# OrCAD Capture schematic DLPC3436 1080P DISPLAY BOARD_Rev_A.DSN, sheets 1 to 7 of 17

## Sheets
1 P10: DMD Connection: size D
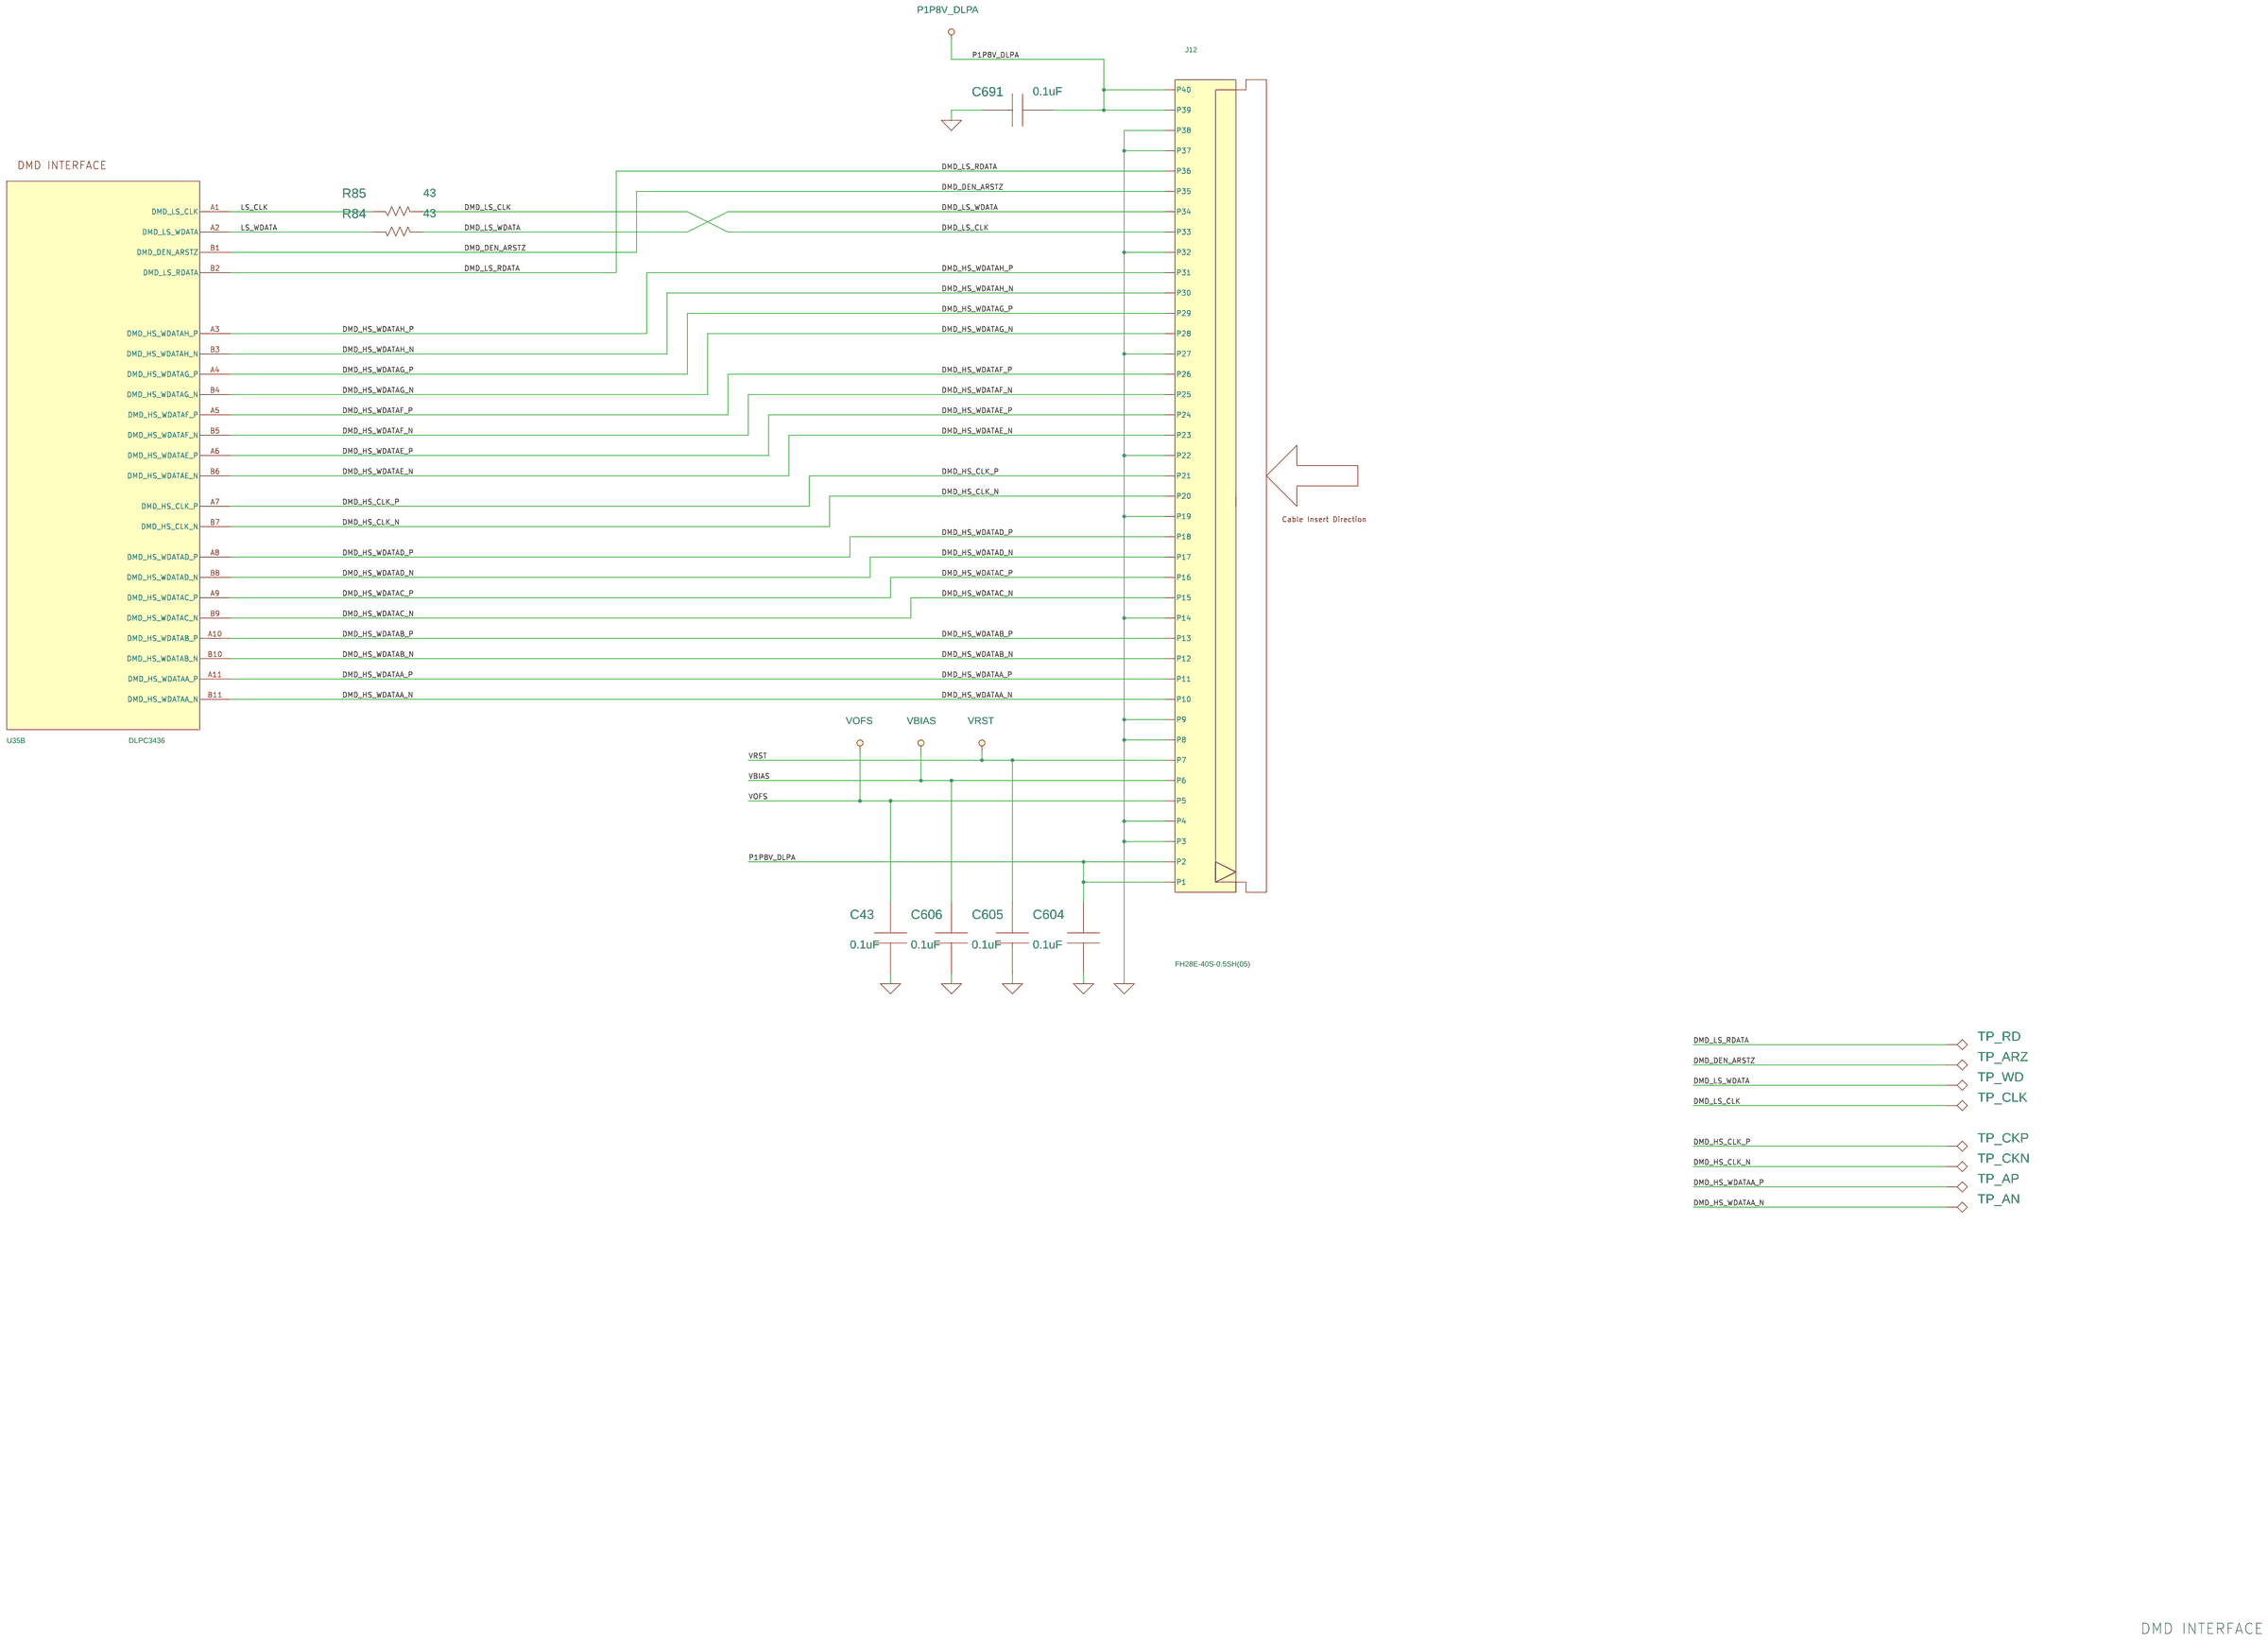
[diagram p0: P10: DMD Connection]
2 P08: FPGA Power: size D
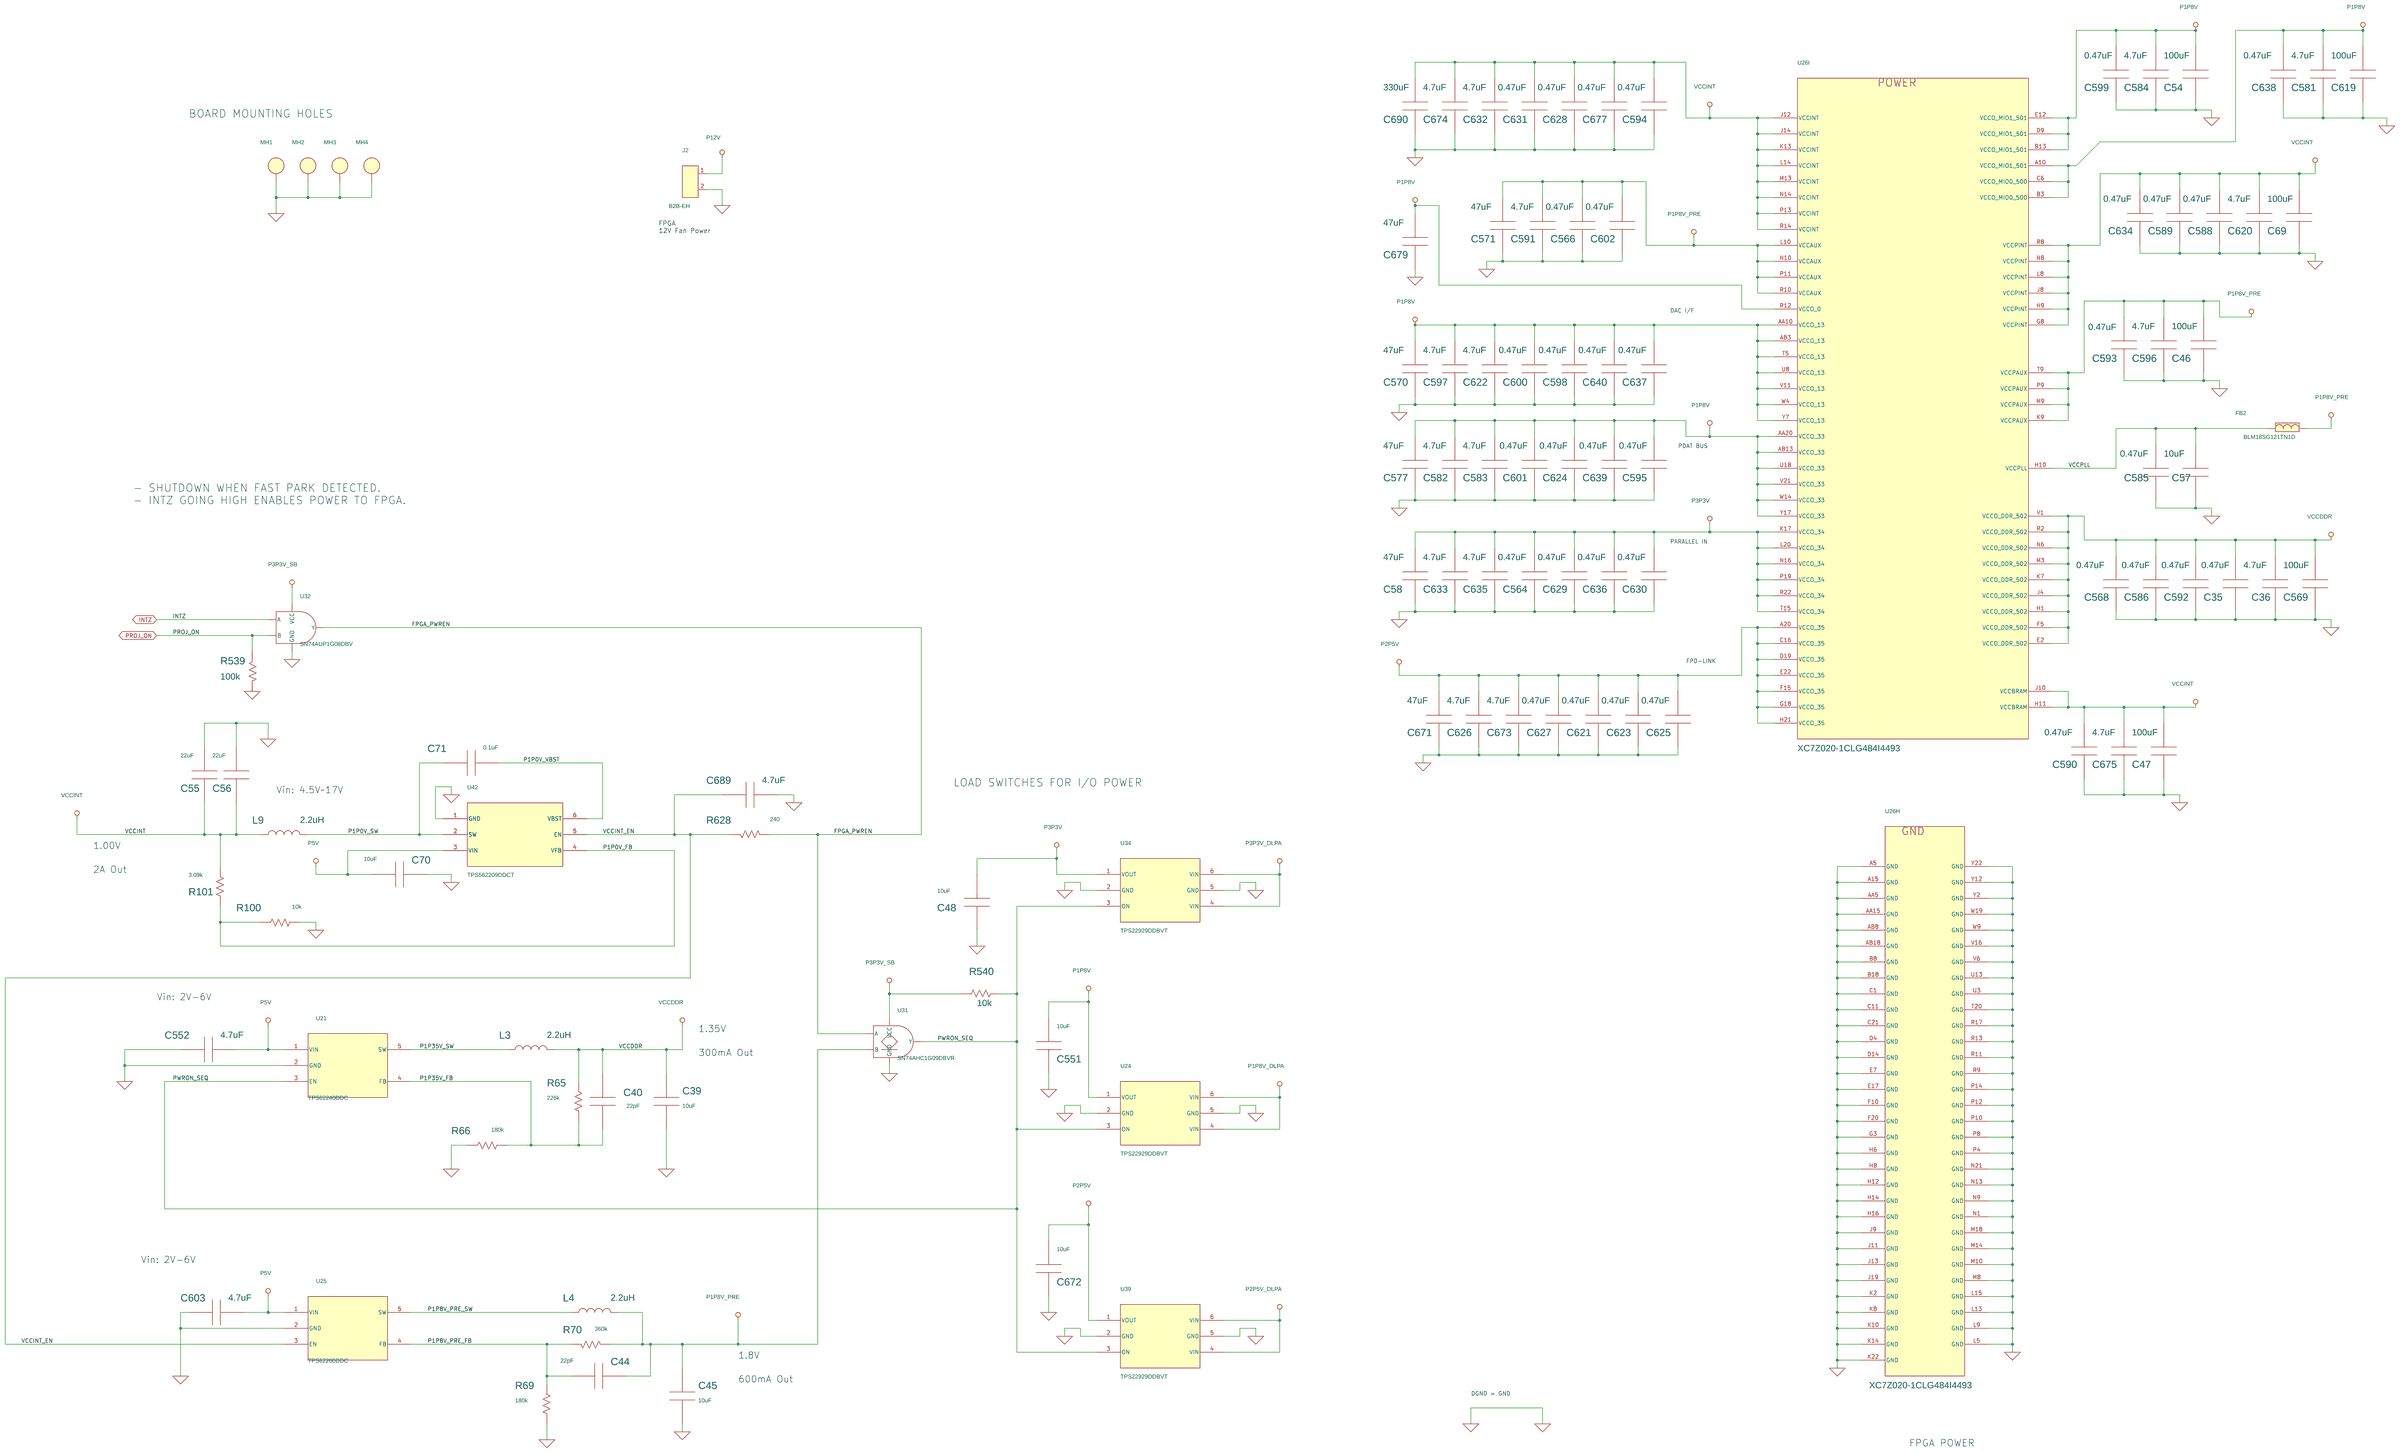
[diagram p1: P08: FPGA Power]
3 P16: Revisions
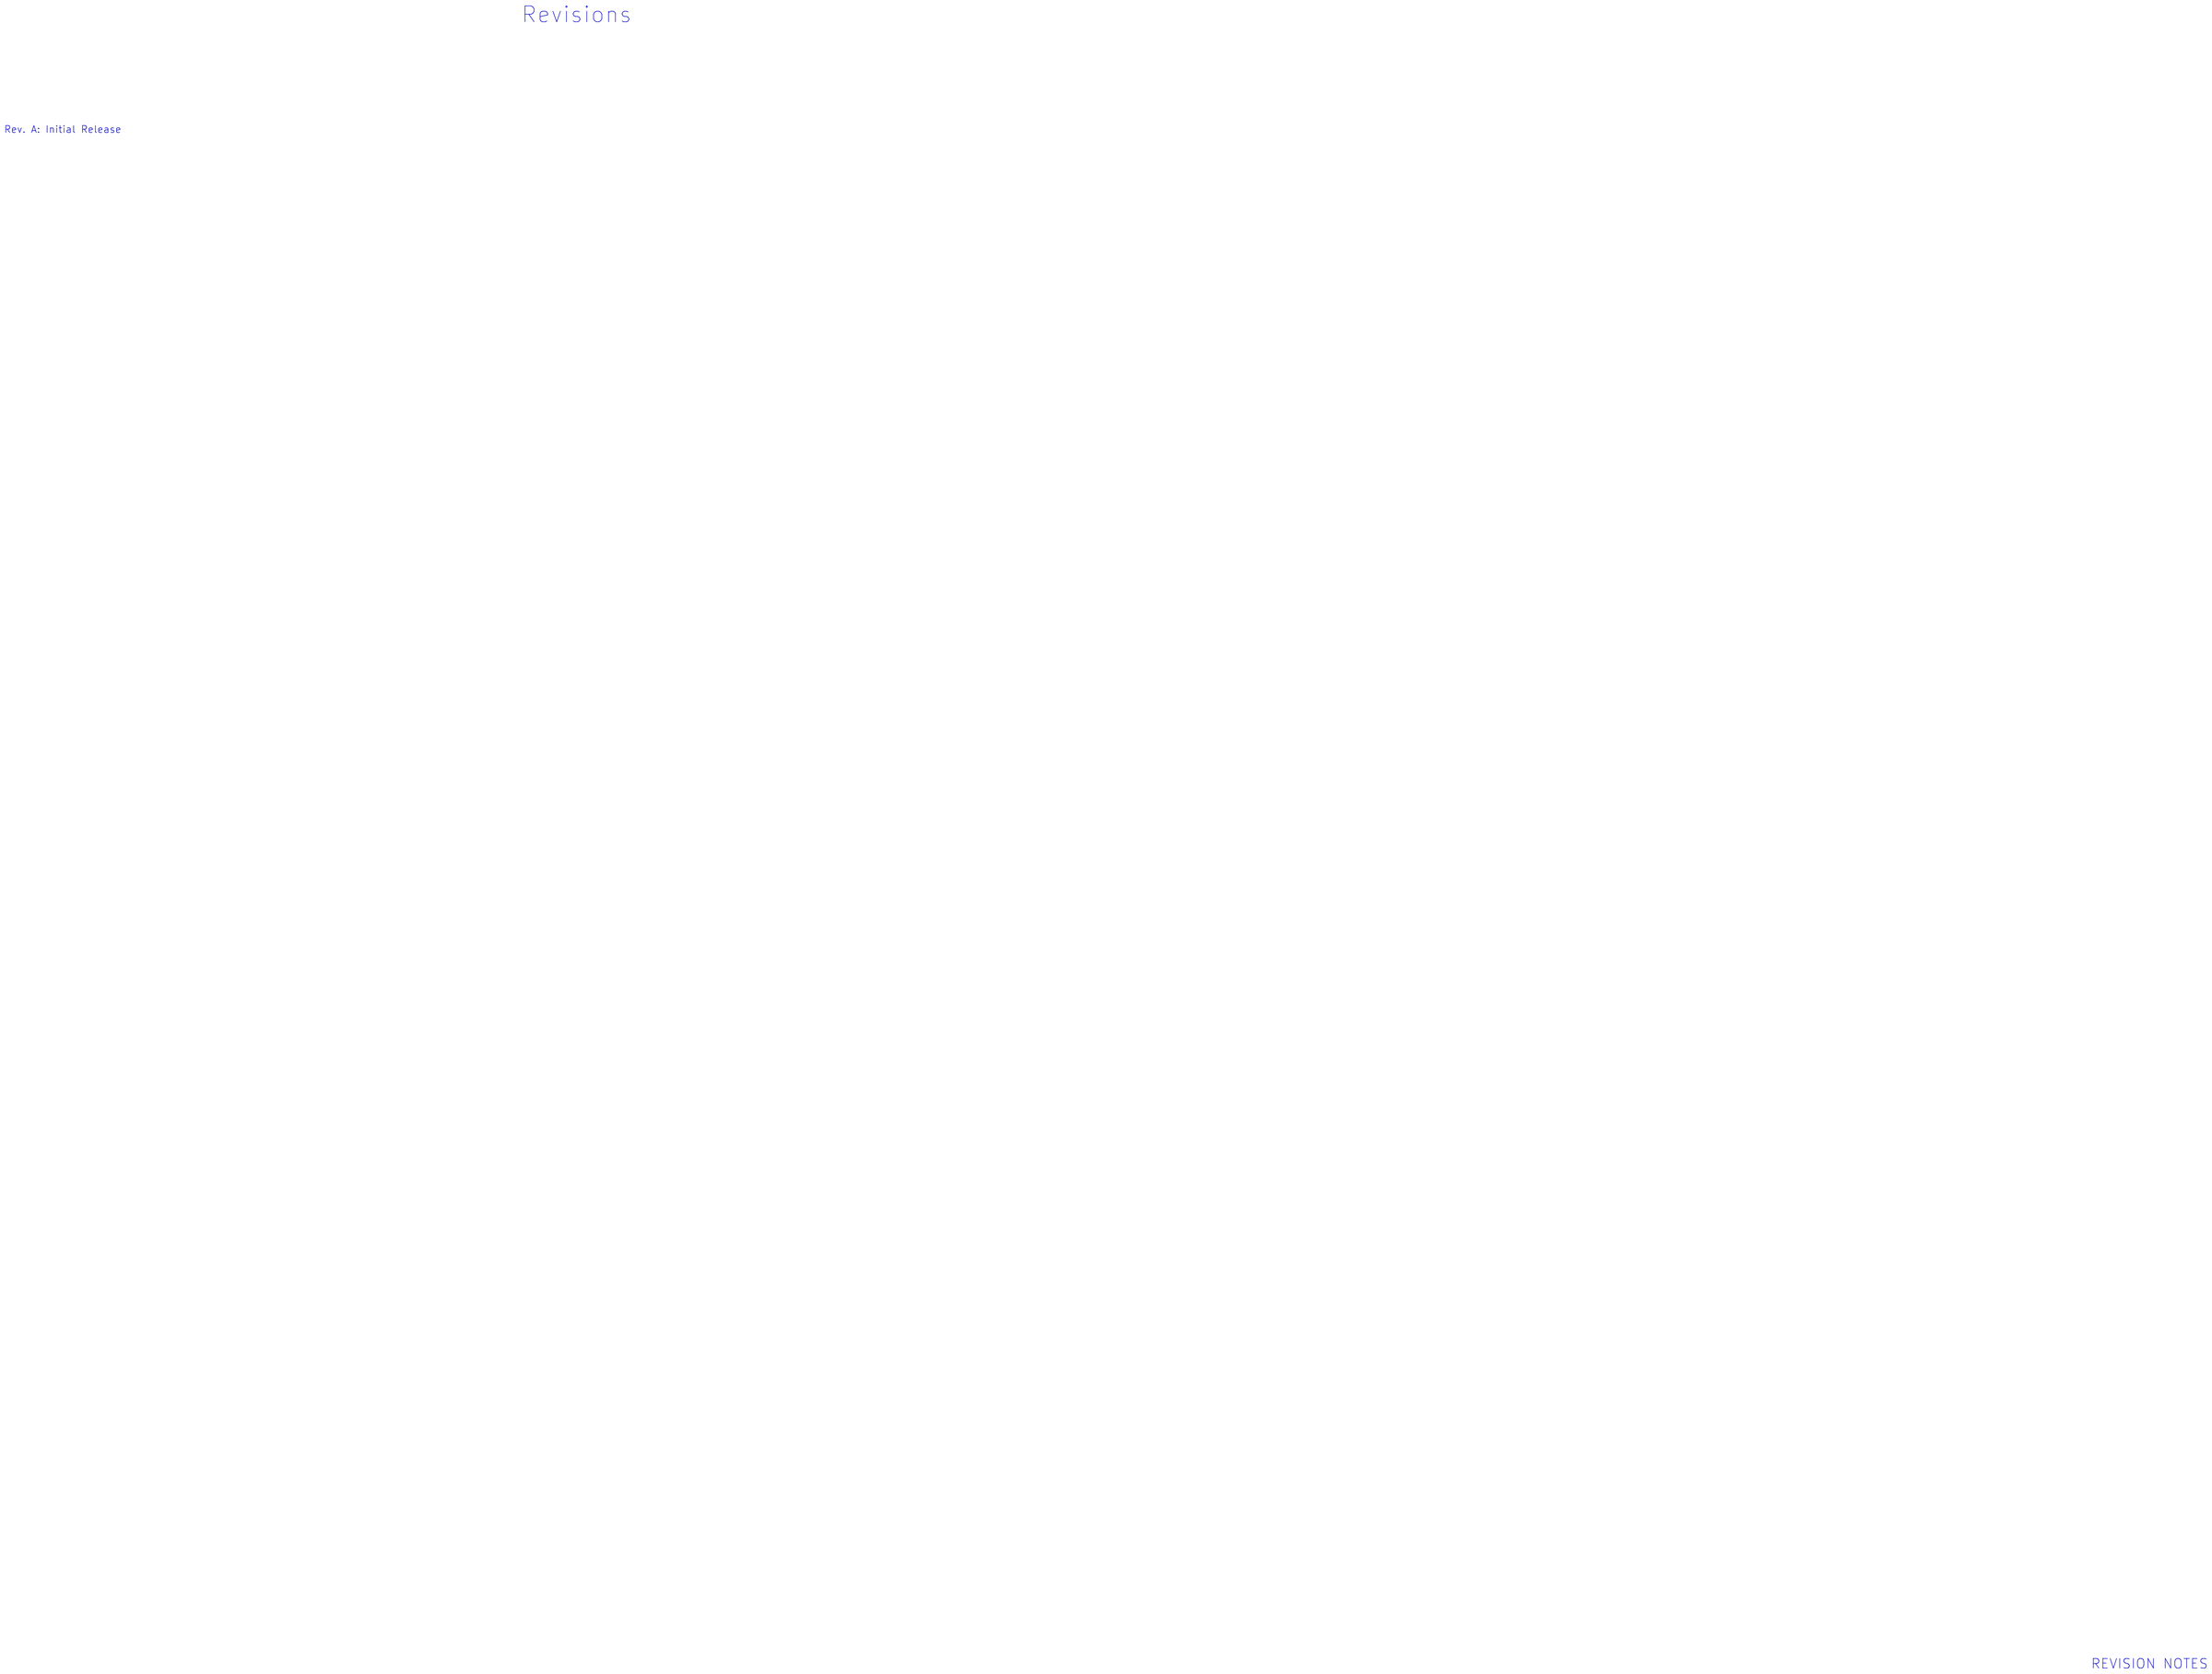
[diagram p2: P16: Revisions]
4 P11: ASIC GPIO: size D
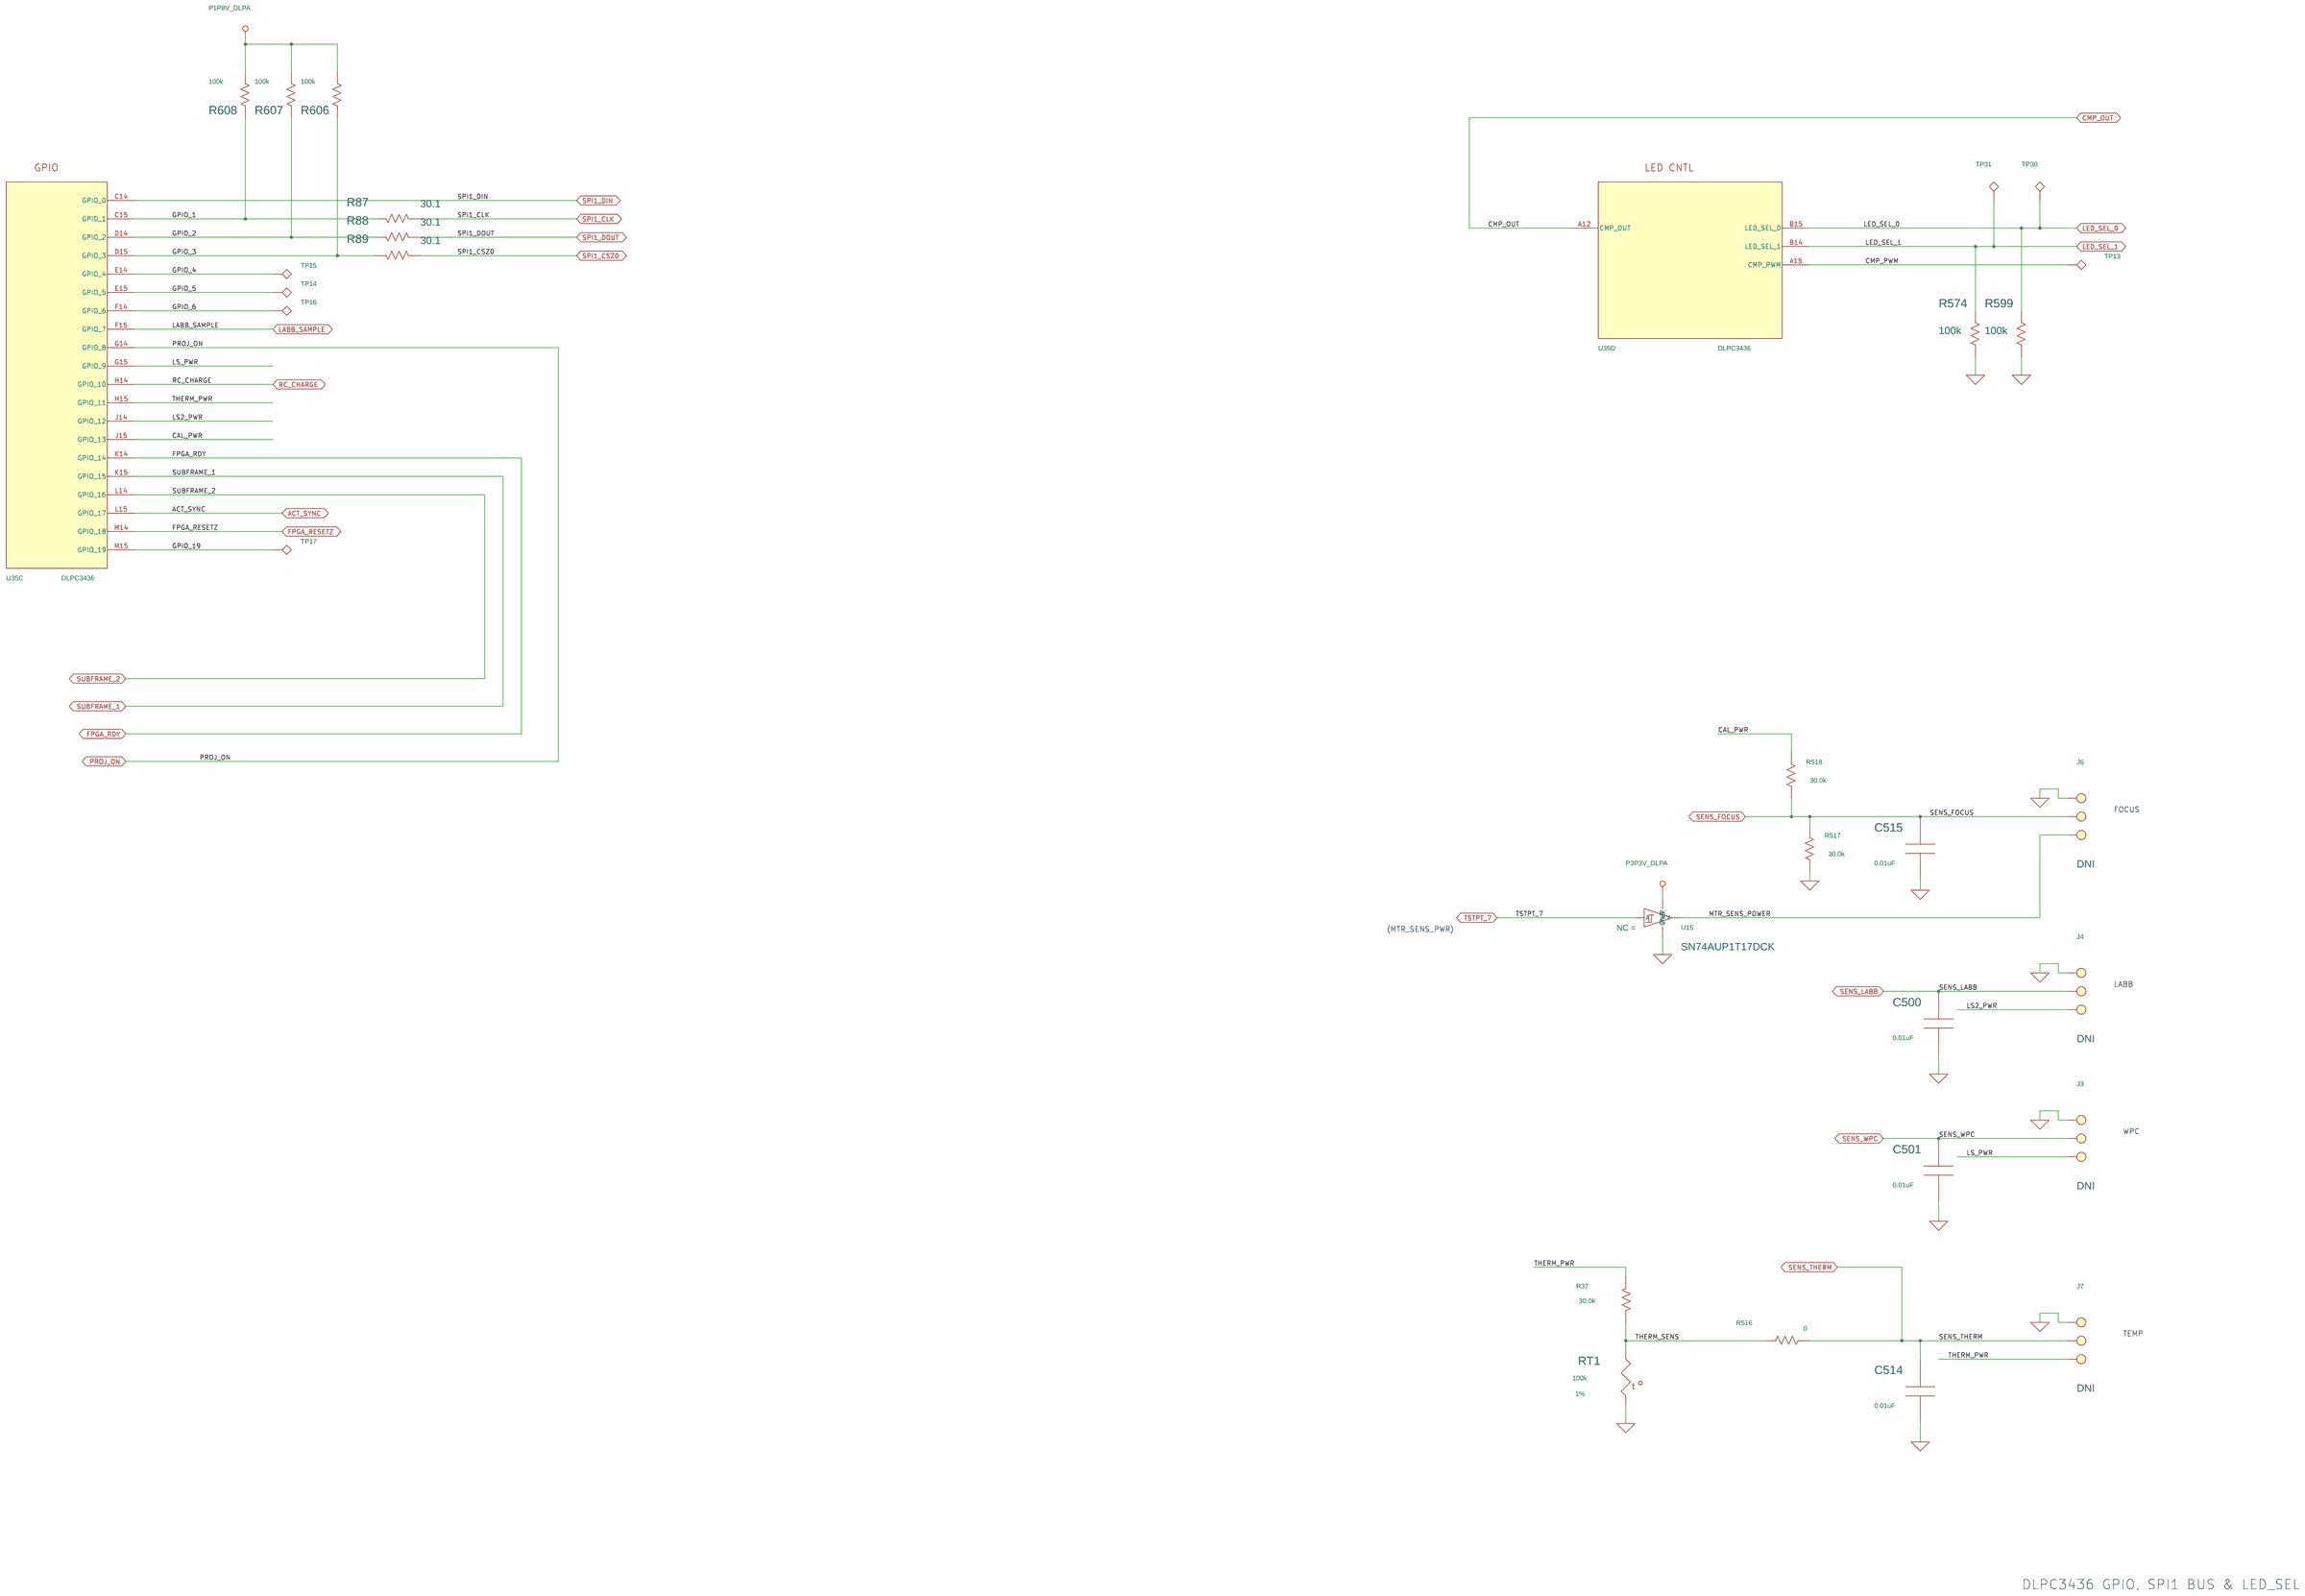
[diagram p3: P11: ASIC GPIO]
5 P01: Title Page: rev: A
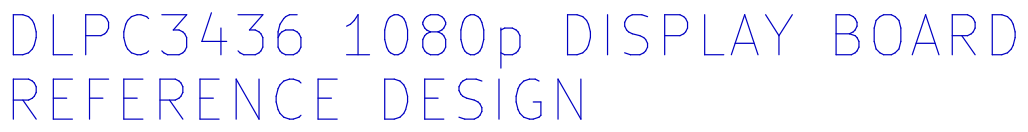
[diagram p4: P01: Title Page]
6 P17: Disclaimer
7 P13: ASIC Power: size D
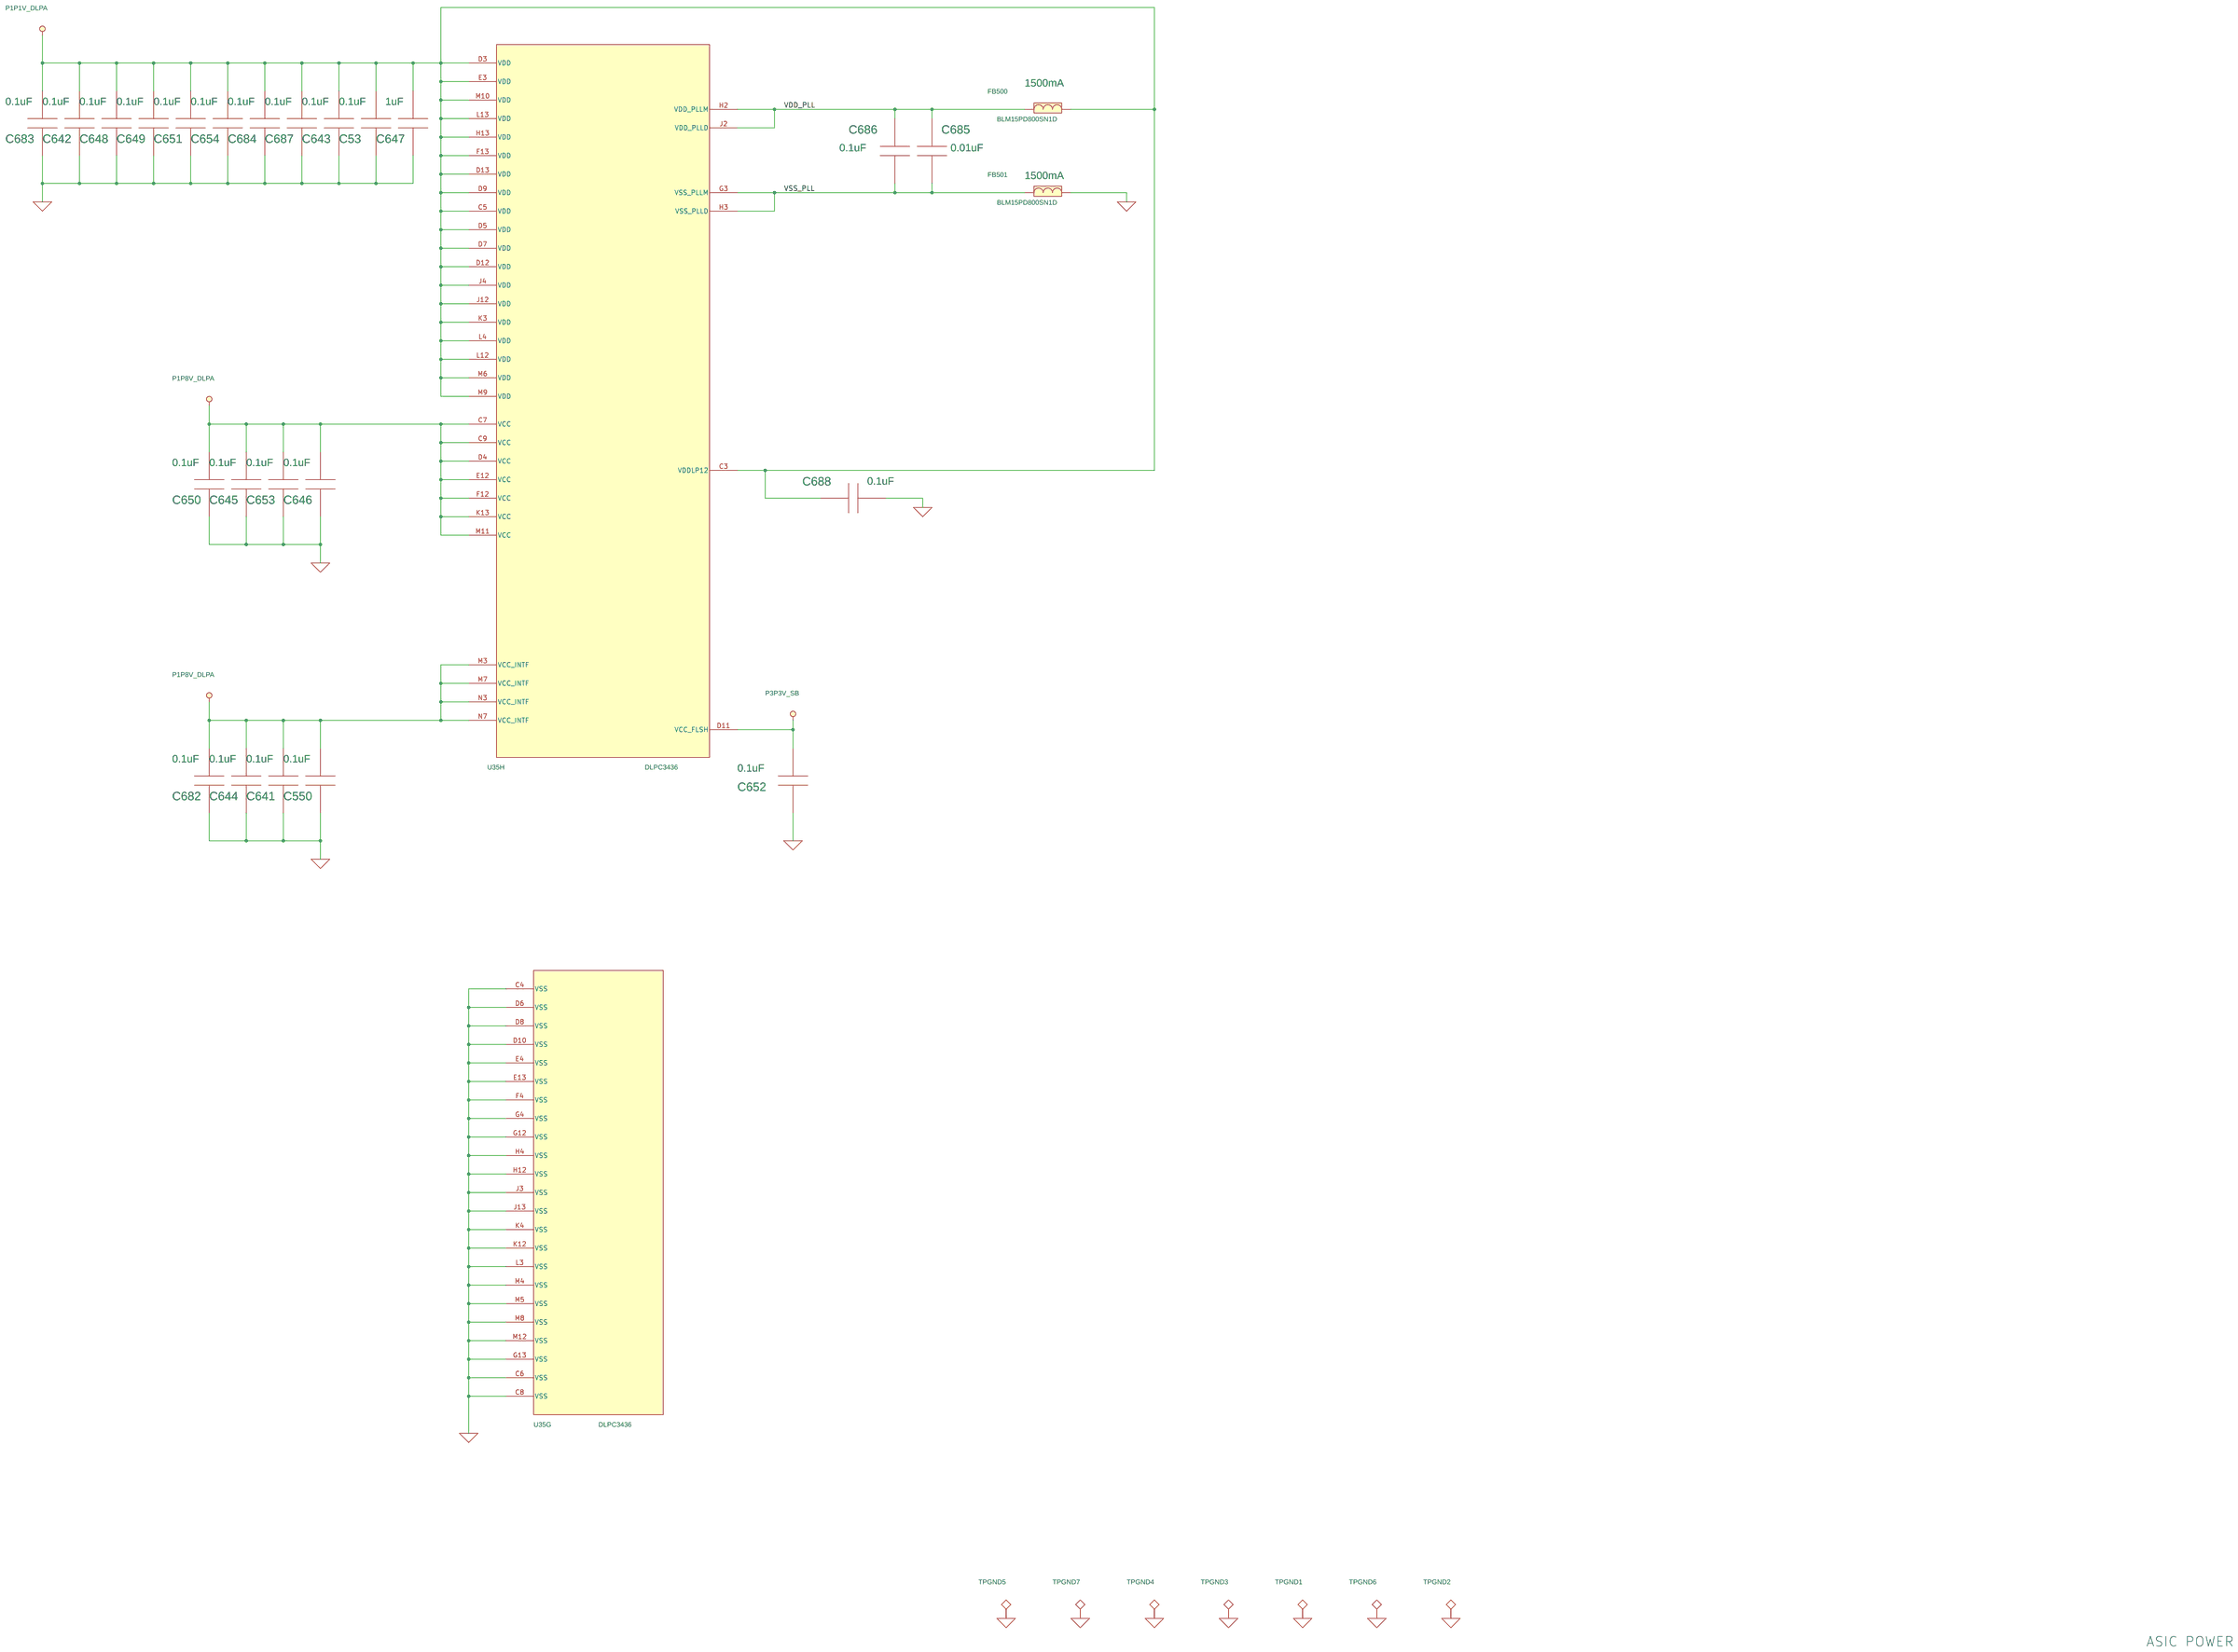
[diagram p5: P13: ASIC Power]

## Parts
sheet P03: Parallel Video Input
U26  XC7Z020-1CLG484I4493  [Xilinx_CLG484]  (sections A,B,C,D,E,F,G,H,I,J)
sheet P08: FPGA Power
C35  0.47uF  [0402]
C36  4.7uF  [0402]
C39  10uF  [0603]
C40  22pF  [0402]
C44  22pF  [0402]
C45  10uF  [0603]
C46  100uF  [0805]
C47  100uF  [0805]
C48  10uF  [0603]
C54  100uF  [0805]
C55  22uF  [0603]
C56  22uF  [0603]
C57  10uF  [0603]
C58  47uF  [0805]
C69  100uF  [0805]
C70  10uF  [0603]
C71  0.1uF  [0402_AVXA]
C551  10uF  [0603]
C552  4.7uF  [0402]
C564  0.47uF  [0402]
C566  0.47uF  [0402]
C568  0.47uF  [0402]
C569  100uF  [0805]
C570  47uF  [0805]
C571  47uF  [0805]
C577  47uF  [0805]
C581  4.7uF  [0402]
C582  4.7uF  [0402]
C583  4.7uF  [0402]
C584  4.7uF  [0402]
C585  0.47uF  [0402]
C586  0.47uF  [0402]
C588  0.47uF  [0402]
C589  0.47uF  [0402]
C590  0.47uF  [0402]
C591  4.7uF  [0402]
C592  0.47uF  [0402]
C593  0.47uF  [0402]
C594  0.47uF  [0402]
C595  0.47uF  [0402]
C596  4.7uF  [0402]
C597  4.7uF  [0402]
C598  0.47uF  [0402]
C599  0.47uF  [0402]
C600  0.47uF  [0402]
C601  0.47uF  [0402]
C602  0.47uF  [0402]
C603  4.7uF  [0402]
C619  100uF  [0805]
C620  4.7uF  [0402]
C621  0.47uF  [0402]
C622  4.7uF  [0402]
C623  0.47uF  [0402]
C624  0.47uF  [0402]
C625  0.47uF  [0402]
C626  4.7uF  [0402]
C627  0.47uF  [0402]
C628  0.47uF  [0402]
C629  0.47uF  [0402]
C630  0.47uF  [0402]
C631  0.47uF  [0402]
C632  4.7uF  [0402]
C633  4.7uF  [0402]
C634  0.47uF  [0402]
C635  4.7uF  [0402]
C636  0.47uF  [0402]
C637  0.47uF  [0402]
C638  0.47uF  [0402]
C639  0.47uF  [0402]
C640  0.47uF  [0402]
C671  47uF  [0805]
C672  10uF  [0603]
C673  4.7uF  [0402]
C674  4.7uF  [0402]
C675  4.7uF  [0402]
C677  0.47uF  [0402]
C679  47uF  [0805]
C689  4.7uF  [0402]
C690  330uF  [1210]
FB2  BLM18SG121TN1D  [0603]
J2  B2B-EH  [JST_B2B_EH_A]
L3  2.2uH  [1008_2p5mmx2mm]
L4  2.2uH  [1008_2p5mmx2mm]
L9  2.2uH  [Coilcraft_XFL4020]
MH1  MOUNTING_HOLE  [MH147-276GND]
MH2  MOUNTING_HOLE  [MH147-276GND]
MH3  MOUNTING_HOLE  [MH147-276GND]
MH4  MOUNTING_HOLE  [MH147-276GND]
R65  226k  [0402]
R66  180k  [0402]
R69  180k  [0402]
R70  360k  [0402]
R100  10k  [0402]
R101  3.09k  [0402]
R539  100k  [0402]
R540  10k  [0402]
R628  240  [0402]
U21  TPS62240DDC  [TSOT-23_DDC_R-PDSO-G5]
U24  TPS22929DDBVT  [SOT23-6_DBV_R-PDSO-G6]
U25  TPS62260DDC  [TSOT-23_DDC_R-PDSO-G5]
U31  SN74AHC1G09DBVR  [SC70_DBV_R-PDSO-G5]
U32  SN74AUP1G08DBV  [SC70_DBV_R-PDSO-G5]
U34  TPS22929DDBVT  [SOT23-6_DBV_R-PDSO-G6]
U39  TPS22929DDBVT  [SOT23-6_DBV_R-PDSO-G6]
U42  TPS562209DDCT  [SOT-23_DDC_R-PDSO-G6]
sheet P10: DMD Connection
C43  0.1uF  [0402]
C604  0.1uF  [0402_AVXA]
C605  0.1uF  [0402]
C606  0.1uF  [0402]
C691  0.1uF  [0402_AVXA]
J12  FH28E-40S-0.5SH(05)  [Hirose_FH28E-40S-0p5SH]
R84  43  [0201]
R85  43  [0201]
TP_AN  20mil_Test_Pad  [20mils_PAD_Testpoint]
TP_AP  20mil_Test_Pad  [20mils_PAD_Testpoint]
TP_ARZ  20mil_Test_Pad  [20mils_PAD_Testpoint]
TP_CKN  20mil_Test_Pad  [20mils_PAD_Testpoint]
TP_CKP  20mil_Test_Pad  [20mils_PAD_Testpoint]
TP_CLK  20mil_Test_Pad  [20mils_PAD_Testpoint]
TP_RD  20mil_Test_Pad  [20mils_PAD_Testpoint]
TP_WD  20mil_Test_Pad  [20mils_PAD_Testpoint]
U35  DLPC3436  [DLPC3436_176NFBGA]  (sections A,B,C,D,E,F,G,H)
sheet P11: ASIC GPIO
C500  0.01uF  [0402]
C501  0.01uF  [0402]
C514  0.01uF  [0402]
C515  0.01uF  [0402]
J3  M20-9990345  [TSW-103-07-G-S]
J4  M20-9990345  [TSW-103-07-G-S]
J6  M20-9990345  [TSW-103-07-G-S]
J7  M20-9990345  [TSW-103-07-G-S]
R37  30.0k  [0402]
R87  30.1  [0402]
R88  30.1  [0402]
R89  30.1  [0402]
R516  0  [0402]
R517  30.0k  [0402]
R518  30.0k  [0402]
R574  100k  [0402]
R599  100k  [0402]
R606  100k  [0402]
R607  100k  [0402]
R608  100k  [0402]
RT1  100k  [0402]
TP13  TP,40mil Drill,60mil Pad  [HOLE_PLATED_40mil_DRILL_60mil_PAD]
TP14  TP,12mil Drill,32mil Pad  [HOLE_PLATED_12mil_DRILL_32mil_PAD]
TP15  TP,12mil Drill,32mil Pad  [HOLE_PLATED_12mil_DRILL_32mil_PAD]
TP16  TP,12mil Drill,32mil Pad  [HOLE_PLATED_12mil_DRILL_32mil_PAD]
TP17  TP,12mil Drill,32mil Pad  [HOLE_PLATED_12mil_DRILL_32mil_PAD]
TP30  TP_WHT  [KEYSTONE_TP_MINIATURE]
TP31  TP_WHT  [KEYSTONE_TP_MINIATURE]
U15  SN74AUP1T17DCK  [U_5_DCK]
sheet P13: ASIC Power
C53  0.1uF  [0402_AVXA]
C550  0.1uF  [0402_AVXA]
C641  0.1uF  [0402_AVXA]
C642  0.1uF  [0402_AVXA]
C643  0.1uF  [0402_AVXA]
C644  0.1uF  [0402_AVXA]
C645  0.1uF  [0402_AVXA]
C646  0.1uF  [0402_AVXA]
C647  1uF  [0402]
C648  0.1uF  [0402_AVXA]
C649  0.1uF  [0402_AVXA]
C650  0.1uF  [0402_AVXA]
C651  0.1uF  [0402_AVXA]
C652  0.1uF  [0402_AVXA]
C653  0.1uF  [0402_AVXA]
C654  0.1uF  [0402_AVXA]
C682  0.1uF  [0402_AVXA]
C683  0.1uF  [0402_AVXA]
C684  0.1uF  [0402_AVXA]
C685  0.01uF  [0402]
C686  0.1uF  [0402_AVXA]
C687  0.1uF  [0402_AVXA]
C688  0.1uF  [0402_AVXA]
FB500  BLM15PD800SN1D  [BLM15P]
FB501  BLM15PD800SN1D  [BLM15P]
TPGND1  TP_BLK  [KEYSTONE_TP_MINIATURE]
TPGND2  TP_BLK  [KEYSTONE_TP_MINIATURE]
TPGND3  TP_BLK  [KEYSTONE_TP_MINIATURE]
TPGND4  TP_BLK  [KEYSTONE_TP_MINIATURE]
TPGND5  TP_BLK  [KEYSTONE_TP_MINIATURE]
TPGND6  TP_BLK  [KEYSTONE_TP_MINIATURE]
TPGND7  TP_BLK  [KEYSTONE_TP_MINIATURE]

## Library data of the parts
U26 = TIDLP,XPR_FPGA,Zynq-7020new_0: DigiKey: ---; DigiReel: ---; Family: processor; Index PN: 1304; Lead Style: SMT; MFG: Xilinx; Type: dlp; Vendor: Xilinx
C35 C564 C566 C568 C585 C586 C588-C590 C592-C595 C598-C602 C621 C623-C625 C627-C631 C634 C636-C640 C677 = PAS,CAP,NP,large: DigiKey: 490-13421-1-ND; DigiReel: 490-13421-6-ND; Family: passive; Lead Style: SMT; MFG: Murata; Material: x5r; P/D_NUM: GRM155R61C474KE01D; Part Number: GRM155R61C474KE01D; Part Specific: CAP CER 0.47UF 16V 10% X5R 0402; TOLERANCE: 10%; Type: capacitor; VENDOR: Murata; VPC: 16V
C36 C552 C581-C584 C591 C596 C597 C603 C620 C622 C626 C632 C633 C635 C673-C675 = PAS,CAP,NP,large: DigiKey: 445-7395-1-ND; DigiReel: 445-7395-6-ND; Family: passive; Index PN: 1073; Lead Style: SMT; MFG: TDK; Material: x5r; P/D_NUM: C1005X5R0J475M; Part Number: C1005X5R0J475M; Part Specific: CAP CER 4.7UF 6.3V 20% X5R 0402; Type: capacitor; VENDOR: TDK; VPC: 6.3V
C39 C45 C48 C57 C551 C672 = PAS,CAP,NP,large: DigiKey: 445-4112-1-ND; DigiReel: 445-4112-6-ND; Family: passive; Index PN: 906; Lead Style: SMT; MFG: TDK; Material: x5r; P/D_NUM: C1608X5R0J106M080AB; Part Number: C1608X5R0J106M080AB; Part Specific: CAP CER 10UF 6.3V 20% X5R 0603; TOLERANCE: 20%; Type: capacitor; VENDOR: TDK; VPC: 6.3V
C40 C44 = PAS,CAP,NP,large: DigiKey: 490-5868-1-ND; DigiReel: 490-5868-6-ND; Family: passive; Lead Style: SMT; MFG: Murata; Material: npo; P/D_NUM: GRM1555C1H220JA01D; Part Number: GRM1555C1H220JA01D; Part Specific: CAP CER 22PF 50V 5% NP0 0402; TOLERANCE: 5%; Type: capacitor; VENDOR: Murata; VPC: 50V
C46 C47 C54 C69 C569 C619 = PAS,CAP,NP,large: DigiKey: 490-10510-1-ND; DigiReel: 490-10510-6-ND; Family: passive; Index PN: 1352; Lead Style: SMT; MFG: Murata; P/D_NUM: GRM21BR60G107ME15L; Part Number: GRM21BR60G107ME15L; Part Specific: CAP CER 100UF 4V 20% X5R 0805; TOLERANCE: 20%; Type: capacitor; VENDOR: Murata; VPC: 4V
C55 C56 = PAS,CAP,NP,large: DigiKey: 445-9077-1-ND; DigiReel: 445-9077-6-ND; Family: passive; Index PN: 1203; Lead Style: SMT; MFG: TDK; Material: x5r; P/D_NUM: C1608X5R1A226M080AC; Part Number: C1608X5R1A226M080AC; Part Specific: CAP CER 22UF 10V 20% X5R 0603; TOLERANCE: 20%; Type: capacitor; VENDOR: TDK; VPC: 10V
C58 C570 C571 C577 C671 C679 = PAS,CAP,NP,large: DigiKey: 445-8239-1-ND; DigiReel: 445-8239-6-ND; Family: passive; Index PN: 1350; Lead Style: SMT; MFG: TDK; P/D_NUM: C2012X5R1A476M125AC; Part Number: C2012X5R1A476M125AC; Part Specific: CAP CER 47UF 10V 20% X5R 0805; TOLERANCE: 20%; Type: capacitor; VENDOR: TDK; VPC: 10V
C70 = PAS,CAP,NP,large: DigiKey: 445-6853-1-ND; DigiReel: 445-6853-6-ND; Family: passive; Index PN: 1207; Lead Style: SMT; MFG: TDK; P/D_NUM: C1608X5R1A106M080AC; Part Number: C1608X5R1A106M080AC; Part Specific: CAP CER 10UF 10V 20% X5R 0603; TOLERANCE: 20%; Type: capacitor; VENDOR: TDK; VPC: 10V; Voltage: 10V
C53 C71 C550 C604 C641-C646 C648-C654 C682-C684 C686-C688 C691 = PAS,CAP,NP,large: DigiKey: 445-4952-1-ND; DigiReel: 445-4952-6-ND; Family: passive; Index PN: 681; Lead Style: SMT; MFG: TDK; Material: x7r; P/D_NUM: C1005X7R1C104K050BC; Part Number: C1005X7R1C104K050BC; Part Specific: CAP CER .1UF 16V X7R 0402; TOLERANCE: 10%; Type: capacitor; VENDOR: TDK; VPC: 16V
C689 = PAS,CAP,NP,large: DigiKey: 445-7395-1-ND; DigiReel: 445-7395-6-ND; Family: passive; Index PN: 1073; Install: Y; Lead Style: SMT; MFG: TDK; Material: x5r; P/D_NUM: C1005X5R0J475M; Part Number: C1005X5R0J475M; Part Specific: CAP CER 4.7UF 6.3V 20% X5R 0402; Type: capacitor; VENDOR: TDK; VPC: 6.3V
C690 = PAS,CAP,NP,large: DigiKey: 587-3977-1-ND; DigiReel: 587-3977-6-ND; Family: passive; Index PN: 1351; Lead Style: SMT; MFG: Taiyo Yuden; P/D_NUM: AMK325ABJ337MM-T; Part Number: AMK325ABJ337MM-T; Part Specific: CAP CER 330UF 4V 20% X5R 1210; TOLERANCE: 20%; Type: capacitor; VENDOR: Taiyo Yuden; VPC: 4V
FB2 = PAS,FERRITE_BEAD,3: DigiKey: 490-3996-1-ND; DigiReel: 490-3996-6-ND; Family: passive; Index PN: 1312; Install: Y; Lead Style: SMT; MFG: Murata; Part Specific: FERRITE BEAD 120 OHM 0603; Type: ferrite bead; VENDOR: Murata; VPC: 3A
J2 = EM,HDR,2P,1R: DigiKey: 455-1611-ND; DigiReel: ---; Family: electro/mechanical; Lead Style: SMT; MFG: JST; P/D_NUM: B2B-EH-A(LF)(SN); Package: HDR_EH_A_2; Part Number: B2B-EH-A(LF)(SN); Part Specific: CONN HEADER EH TOP 2POS 2.5MM; Pin Cnt: 2; Pin Spacing: 2.5mm; Row Cnt: 1; Type: header; Vendor: JST
L3 L4 = PAS,INDUCTOR,_large: DigiKey: 490-5114-1-ND; DigiReel: 490-5114-6-ND; Family: passive; Index PN: 1149; Install: Y; Lead Style: SMT; MFG: Murata; P/D_NUM: LQM2HPN2R2MG0L; Part Number: LQM2HPN2R2MG0L; Part Specific: INDUCTOR 2.2UH 20% 1300MA 1008; Type: inductor; VENDOR: Murata
L9 = PAS,INDUCTOR,_large: Family: passive; Install: Y; Lead Style: SMT; MFG: CoilCraft; P/D_NUM: XFL4020-222MEB; Part Number: XFL4020-222MEB; Part Specific: INDUCTOR 2.2UH 20% 3.1A; Type: inductor; VENDOR: Coilcraft
MH1-MH4 = MOUNTING_HOLE: Install: DNI; Part Number: -- NOT A PART --; Part Specific: MOUNTING HOLE
R65 = PAS,R,large: DigiKey: P226KLCT-ND; DigiReel: P226KLDKR-ND; Family: passive; Lead Style: SMT; MFG: Panasonic; P/D_NUM: ERJ-2RKF2263X; Part Number: ERJ-2RKF2263X; Part Specific: RES SMD 226K OHM 1% 1/10W 0402; TOLERANCE: 1%; Type: resistor; VENDOR: Panasonic; VPC: 1/10W
R66 R69 = PAS,R,large: DigiKey: 311-180KLRCT-ND; DigiReel: 311-180KLRDKR-ND; Family: passive; Index PN: 1179; Lead Style: SMT; MFG: Yageo; P/D_NUM: RC0402FR-07180KL; Part Number: RC0402FR-07180KL; Part Specific: RES SMD 180K OHM 1% 1/16W 0402; TOLERANCE: 1%; Type: resistor; VENDOR: Yageo; VPC: 1/16W
R70 = PAS,R,large: DigiKey: P360KLCT-ND; DigiReel: P360KLDKR-ND; Family: passive; Lead Style: SMT; MFG: Panasonic; P/D_NUM: ERJ-2RKF3603X; Part Number: ERJ-2RKF3603X; Part Specific: RES SMD 360K OHM 1% 1/10W 0402; TOLERANCE: 1%; Type: resistor; VENDOR: Panasonic; VPC: 1/10W
R100 = PAS,R,large: DigiKey: P10.0KLCT-ND; DigiReel: P10.0KLDKR-ND; Family: passive; Index PN: 680; Lead Style: SMT; MFG: Panasonic; Material: chip; P/D_NUM: ERJ-2RKF1002X; Part Number: ERJ-2RKF1002X; Part Specific: RES SMD 10K OHM 1% 1/10W 0402; Power: 1/16W; TOLERANCE: 1%; Type: resistor; VENDOR: Panasonic; VPC: 1/16W
R101 = PAS,R,large: DigiKey: P3.09KLCT-ND; DigiReel: P3.09KLDKR-ND; Family: passive; Index PN: 1307; Lead Style: SMT; MFG: Panasonic; P/D_NUM: ERJ-2RKF3091X; Part Number: ERJ-2RKF3091X; Part Specific: RES SMD 3.09K OHM 1% 1/10W 0402; Type: resistor; VENDOR: Panasonic; VPC: 1/16W
R539 = PAS,R,large: DigiKey: 541-100KLCT-ND; DigiReel: 541-100KLDKR-ND; Family: passive; Index PN: 712; Lead Style: SMT; MFG: Vishay/Dale; Material: chip; P/D_NUM: CRCW0402100KFKED; Part Number: CRCW0402100KFKED; Part Specific: RES 100K OHM 1/10W 1% 0402 SMD; Power: 1/16W; TOLERANCE: 1%; Type: resistor; VPC: 1/16W; Vendor: Vishay/Dale
R540 = PAS,R,large: DigiKey: P10.0KLCT-ND; DigiReel: P10.0KLDKR-ND; Family: passive; Index PN: 680; Install: Y; Lead Style: SMT; MFG: Panasonic; Material: chip; P/D_NUM: ERJ-2RKF1002X; Part Number: ERJ-2RKF1002X; Part Specific: RES SMD 10K OHM 1% 1/10W 0402; Power: 1/16W; TOLERANCE: 1%; Type: resistor; VPC: 1/16W; Vendor: Panasonic
R628 = PAS,R,large: DigiKey: P240LCT-ND; DigiReel: P240LDKR-ND; Family: passive; Index PN: 1303; Lead Style: SMT; MFG: Panasonic; P/D_NUM: ERJ-2RKF2400X; Part Number: ERJ-2RKF2400X; Part Specific: RES SMD 240 OHM 1% 1/10W 0402; Type: resistor; VENDOR: Panasonic; VPC: 1/16W
U21 = PWR,REG,TPS62240,TSOT23_DDC: DigiKey: 296-41858-1-ND; DigiReel: 296-41858-6-ND; Install: Y; Lead Style: SMT; MFG: Texas Instruments; P/D_NUM: TPS62240DDCR; Part Number: TPS62240DDCR; Part Specific: IC REG BUCK ADJ 0.3A SYNC TSOT23; Pin Cnt: 5; Type: regulator; Vendor: Texas Instruments
U24 U34 U39 = PWR,SW,TPS22929DDBV: DigiKey: 296-30174-1-ND; DigiReel: 296-30174-6-ND; Family: power; Index PN: 1309; Lead Style: SMT; MFG: Texas Instruments; Part Specific: IC LOAD SWITCH SOT23-6; Type: switch; Vendor: Texas Instruments
U25 = PWR,REG,TPS62240,TSOT23_DDC: DigiKey: 296-39455-1-ND; DigiReel: 296-39455-6-ND; Install: Y; Lead Style: SMT; MFG: Texas Instruments; P/D_NUM: TPS62260DDCR; Part Number: TPS62260DDCR; Part Specific: IC REG BUCK ADJ 0.6A SYNC TSOT23; Pin Cnt: 5; Type: regulator; Vendor: Texas Instruments
U31 = LOG,AND,OPENDRN,Tiny_Logic: DigiKey: 296-29202-1-ND; DigiReel: 296-29202-6-ND; Index PN: 1094; Lead Style: SMT; MFG: Texas Instruments; Part Specific: IC GATE AND SGL 2INP; Type: and; Vendor: Texas Instruments
U32 = LOG,AND,Tiny_Logic: DigiKey: 296-19074-1-ND; DigiReel: 296-19074-6-ND; Index PN: 1378; Lead Style: SMT; MFG: Texas Instruments; P/D_NUM: SN74AUP1G08DBVR; Part Number: SN74AUP1G08DBVR; Part Specific: IC GATE AND 1CH 2-INP SOT-23-5; Type: and; Vendor: Texas Instruments
U42 = PWR,REG,TPS56x209,SOT23_DDC: DigiKey: 296-37302-2-ND; DigiReel: 296-37302-6-ND; Family: power; Index PN: 1305; Lead Style: SMT; MFG: Texas Instruments; Part Specific: IC REG BUCK ADJ 2A SYNC SOT-23-6; Type: regulator; Vendor: Texas Instruments
C43 C605 C606 = PAS,CAP,NP,large: DigiKey: 587-1456-1-ND; DigiReel: 587-1456-6-ND; Family: passive; Index PN: 922; Lead Style: SMT; MFG: Taiyo Yuden; Material: x5r; P/D_NUM: TMK105BJ104KV-F; Part Number: TMK105BJ104KV-F; Part Specific: CAP CER .10UF 25V X5R 0402; Type: capacitor; VENDOR: Taiyo Yuden; VPC: 25V
J12 = EM,CONN,40P,1R,FLEX,2X: DigiKey: HFV040CT-ND; DigiReel: HFV040DKR-ND; Family: electro/mechanical; Index PN: 1157; Lead Style: SMT; MFG: Hirose; Part Specific: CONN FPC 40POS 0.5MM SMD GOLD; Pin Cnt: 40; Pin Spacing: 0.5mm; Type: connector; Vendor: Hirose
R84 R85 = PAS,R,large: DigiKey: P123325CT-ND; DigiReel: P123325DKR-ND; Family: passive; Lead Style: SMT; MFG: Panasonic; P/D_NUM: ERJ-1GNJ430C; Part Number: ERJ-1GNJ430C; Part Specific: RES 43 OHM 1/20W 5% 0201 SMD; TOLERANCE: 5%; Type: resistor; VENDOR: Panasonic
TP_AN TP_AP TP_ARZ TP_CKN TP_CKP TP_CLK TP_RD TP_WD = EM,TERM,TESTPOINT,_20mil_pad: Family: board feature; Install: DNI; MFG: -- NOT A PART --; Vendor: -- NOT A PART --
U35 = TIDLP,DPP3430: DigiKey: ---; DigiReel: ---; Family: processor; Lead Style: SMT; MFG: Texas Instruments; P/D_NUM: DLPC3436CZVBR; Part Number: DLPC3436CZVBR; Part Specific: DLP PICO CONTROLLER DLPC3436 176NFBGA; Type: dlp; Vendor: Texas Instruments; Install: Y; SPLIT_INST: TRUE
C500 C501 C514 C515 = PAS,CAP,NP,large: DigiKey: 445-1262-1-ND; DigiReel: 445-1262-6-ND; Family: passive; Index PN: 908; Lead Style: SMT; MFG: TDK; Material: x7r; P/D_NUM: C1005X7R1C103K; Part Number: C1005X7R1C103K; Part Specific: CAP CER 10000PF 16V X7R 10% 0402; TOLERANCE: 10%; Type: capacitor; VENDOR: TDK; VPC: 16V; Voltage: 16V
J3 J4 J6 J7 = EM,JMP,3P,1R: DigiKey: 952-2263-ND; DigiReel: ---; Install: DNI; Lead Style: TH; MFG: Harwin; Part Specific: CONN HEADER 3POS .100" SGL GOLD; Pin Cnt: 3; Pin Spacing: 100mil; Row Cnt: 1; Type: header; Vendor: Harwin
R37 R517 R518 = PAS,R,large: DigiKey: P30.0KLCT-ND; DigiReel: P30.0KLDKR-ND; Family: passive; Index PN: 909; Lead Style: SMT; MFG: Panasonic; Material: chip; P/D_NUM: ERJ-2RKF3002X; Part Number: ERJ-2RKF3002X; Part Specific: RES 30.0K OHM 1/10W 1% 0402 SMD; Power: 1/16W; Tolerance: 1%; Type: resistor; VPC: 1/16W; Vendor: Panasonic
R87-R89 = PAS,R,large: DigiKey: P30.1LCT-ND; DigiReel: P30.1LDKR-ND; Family: passive; Index PN: 976; Lead Style: SMT; MFG: Panasonic; Material: chip; P/D_NUM: ERJ-2RKF30R1X; Part Number: ERJ-2RKF30R1X; Part Specific: RES 30.1 OHM 1/16W 1% 0402 SMD; Power: 1/16W; TOLERANCE: 1%; Type: resistor; VENDOR: Panasonic; VPC: 1/16W
R516 = PAS,R,large: DigiKey: P0.0JCT-ND; DigiReel: P0.0JDKR-ND; Family: passive; Index PN: 687; Lead Style: SMT; MFG: Panasonic; Material: chip; P/D_NUM: ERJ-2GE0R00X; Part Number: ERJ-2GE0R00X; Part Specific: RES 0.0 OHM 1/16W 0402 SMD; Power: 1/16W; Type: resistor; VPC: 1/16W; Vendor: Panasonic
R574 R599 R606-R608 = PAS,R,large: DigiKey: 541-100KLCT-ND; DigiReel: 541-100KLDKR-ND; Family: passive; Index PN: 712; Lead Style: SMT; MFG: Vishay/Dale; Material: chip; P/D_NUM: CRCW0402100KFKED; Part Number: CRCW0402100KFKED; Part Specific: RES 100K OHM 1/10W 1% 0402 SMD; Power: 1/16W; TOLERANCE: 1%; Type: resistor; VENDOR: Vishay/Dale; VPC: 1/16W
RT1 = PAS,THERMISTOR,large: DigiKey: 490-4803-1-ND; DigiReel: 490-4803-6-ND; Family: passive; Index PN: 910; Lead Style: SMT; MFG: Murata; P/D_NUM: NCP15WF104F03RC; Part Number: NCP15WF104F03RC; Part Specific: THERMISTOR 100K OHM NTC 0402 SMD; TOLERANCE: 1%; Type: thermistor; VENDOR: Murata
TP13 = BF,HOLE,PLATED,TESTPIN: DigiKey: ---; DigiReel: ---; Family: board feature; Index PN: 377; Install: DNI; Lead Style: TH; MFG: -- NOT A PART --; Type: hole,plated; Vendor: -- NOT A PART --
TP14-TP17 = EM,TERM,TESTPOINT: Family: board feature; Index PN: 122; Install: DNI; MFG: -- NOT A PART --; Type: hole,plated; Vendor: -- NOT A PART --
TP30 TP31 = EM,TERM,TESTPOINT: DigiKey: 36-5002-ND; DigiReel: ---; Family: electro/mechanical; Install: DNI; Lead Style: TH; MFG: Keystone; P/D_NUM: 5002; Part Number: 5002; Part Specific: TEST POINT PC MINI .040inD WHITE; Type: terminal; Vendor: Keystone
U15 = LOG,BUF,SCHMITT,SN74AUP1T17DCK: DigiKey: 296-27395-1-ND; DigiReel: 296-27395-6-ND; Family: logic; Index PN: 1199; Lead Style: SMT; MFG: Texas Instruments; P/D_NUM: SN74AUP1T17DCKR; Part Number: SN74AUP1T17DCKR; Part Specific: IC BUFFER SCHMITT TRIG LP SC70-5; Type: buffer
C647 = PAS,CAP,NP,large: DigiKey: 1276-1448-1-ND; DigiReel: 1276-1448-6-ND; Family: passive; Lead Style: SMT; MFG: Samsung; Material: x5r; P/D_NUM: CL05A105MP5NNNC; Part Number: CL05A105MP5NNNC; Part Specific: CAP CER 1.0UF 10V X5R 0402; TOLERANCE: 20%; Type: capacitor; VENDOR: Samsung; VPC: 10V
C685 = PAS,CAP,NP,large: DigiKey: 445-1262-1-ND; DigiReel: 445-1262-6-ND; Family: passive; Index PN: 908; Lead Style: SMT; MFG: TDK; Material: x7r; P/D_NUM: C1005X7R1C103K; Part Number: C1005X7R1C103K; Part Specific: CAP CER 10000PF 16V X7R 10% 0402; TOLERANCE: 10%; Type: capacitor; VENDOR: TDK; VPC: 16V
FB500 FB501 = PAS,FERRITE_BEAD,3: DigiKey: 490-5202-1-ND; DigiReel: 490-5202-6-ND; Family: passive; Index PN: 999; Install: Y; Lead Style: SMT; MFG: Murata; Part Specific: FERRITE CHIP 80 OHM 1500MA 0402; Type: ferrite bead; VENDOR: Murata; VPC: 1500mA
TPGND1-TPGND7 = EM,TERM,TESTPOINT: DigiKey: 36-5001-ND; DigiReel: ---; Family: electro/mechanical; Index PN: 946; Install: Y; Lead Style: TH; MFG: Keystone; P/D_NUM: 5001; Part Number: 5001; Part Specific: TEST POINT PC MINI .040inD BLACK; Type: terminal; Vendor: Keystone

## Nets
DGND: C35.2(N) C36.2(N) C39.2(N) C43.2(N) C45.2(N) C46.2(N) C47.2(N) C48.2(N) C53.2(N) C54.2(N) C55.1(P) C56.1(P) C57.2(N) C58.2(N) C69.2(N) C70.2(N) C500.2(N) C501.2(N) C514.2(N) C515.2(N) C550.2(N) C551.2(N) C552.1(P) C564.2(N) C566.2(N) C568.2(N) C569.2(N) C570.2(N) C571.2(N) C577.2(N) C581.2(N) C582.2(N) C583.2(N) C584.2(N) C585.2(N) C586.2(N) C588.2(N) C589.2(N) C590.2(N) C591.2(N) C592.2(N) C593.2(N) C594.2(N) C595.2(N) C596.2(N) C597.2(N) C598.2(N) C599.2(N) C600.2(N) C601.2(N) C602.2(N) C603.1(P) C604.2(N) C605.2(N) C606.2(N) C619.2(N) C620.2(N) C621.2(N) C622.2(N) C623.2(N) C624.2(N) C625.2(N) C626.2(N) C627.2(N) C628.2(N) C629.2(N) C630.2(N) C631.2(N) C632.2(N) C633.2(N) C634.2(N) C635.2(N) C636.2(N) C637.2(N) C638.2(N) C639.2(N) C640.2(N) C641.2(N) C642.2(N) C643.2(N) C644.2(N) C645.2(N) C646.2(N) C647.2(N) C648.2(N) C649.2(N) C650.2(N) C651.2(N) C652.2(N) C653.2(N) C654.2(N) C671.2(N) C672.2(N) C673.2(N) C674.2(N) C675.2(N) C677.2(N) C679.2(N) C682.2(N) C683.2(N) C684.2(N) C687.2(N) C688.2(N) C689.2(N) C690.2(N) C691.2(N) FB501.2(N2) J2.2 J3.3 J4.3 J6.3 J7.3 J12.3(P3) J12.4(P4) J12.8(P8) J12.9(P9) J12.14(P14) J12.19(P19) J12.22(P22) J12.27(P27) J12.32(P32) J12.37(P37) J12.38(P38) MH1.1 MH2.1 MH3.1 MH4.1 R66.2(N2) R69.1(N1) R100.1(N1) R517.1(N1) R539.1(N1) R574.1(N1) R599.1(N1) RT1.2 TPGND1.1(P1) TPGND2.1(P1) TPGND3.1(P1) TPGND4.1(P1) TPGND5.1(P1) TPGND6.1(P1) TPGND7.1(P1) U15.3(GND) U21.2(GND) U24.2(GND) U24.5(GND) U25.2(GND) U26.A5(GND) U26.A15(GND) U26.AA5(GND) U26.AA15(GND) U26.AB8(GND) U26.AB18(GND) U26.B8(GND) U26.B18(GND) U26.C1(GND) U26.C11(GND) U26.C21(GND) U26.D4(GND) U26.D14(GND) U26.E7(GND) U26.E17(GND) U26.F10(GND) U26.F20(GND) U26.G3(GND) U26.H6(GND) U26.H8(GND) U26.H12(GND) U26.H14(GND) U26.H16(GND) U26.J9(GND) U26.J11(GND) U26.J13(GND) U26.J19(GND) U26.K2(GND) U26.K8(GND) U26.K10(GND) U26.K14(GND) U26.K22(GND) U26.L5(GND) U26.L9(GND) U26.L13(GND) U26.L15(GND) U26.M8(GND) U26.M10(GND) U26.M14(GND) U26.M18(GND) U26.N1(GND) U26.N9(GND) U26.N13(GND) U26.N21(GND) U26.P4(GND) U26.P8(GND) U26.P10(GND) U26.P12(GND) U26.P14(GND) U26.R9(GND) U26.R11(GND) U26.R13(GND) U26.R17(GND) U26.T20(GND) U26.U3(GND) U26.U13(GND) U26.V6(GND) U26.V16(GND) U26.W9(GND) U26.W19(GND) U26.Y2(GND) U26.Y12(GND) U26.Y22(GND) U31.3(GND) U32.3(GND) U34.2(GND) U34.5(GND) U35.C4(VSS) U35.C6(VSS) U35.C8(VSS) U35.D6(VSS) U35.D8(VSS) U35.D10(VSS) U35.E4(VSS) U35.E13(VSS) U35.F4(VSS) U35.G4(VSS) U35.G12(VSS) U35.G13(VSS) U35.H4(VSS) U35.H12(VSS) U35.J3(VSS) U35.J13(VSS) U35.K4(VSS) U35.K12(VSS) U35.L3(VSS) U35.M4(VSS) U35.M5(VSS) U35.M8(VSS) U35.M12(VSS) U39.2(GND) U39.5(GND) U42.1(GND) ; also on sheet 8 9 10 11 12 13 14 15 16 17
P5V: C70.1(P) C552.2(N) C603.2(N) U21.1(VIN) U25.1(VIN) U42.3(VIN) ; also on sheet 8 9 11
P12V: J2.1 ; also on sheet 10 11
VCCDDR: C35.1(P) C36.1(P) C39.1(P) C40.1(P) C568.1(P) C569.1(P) C586.1(P) C592.1(P) L3.2 R65.2(N2) U26.E2(VCCO_DDR_502) U26.F5(VCCO_DDR_502) U26.H1(VCCO_DDR_502) U26.J4(VCCO_DDR_502) U26.K7(VCCO_DDR_502) U26.M3(VCCO_DDR_502) U26.N6(VCCO_DDR_502) U26.R2(VCCO_DDR_502) U26.V1(VCCO_DDR_502) ; also on sheet 12
VCCINT: C47.1(P) C55.2(N) C56.2(N) C69.1(P) C588.1(P) C589.1(P) C590.1(P) C594.1(P) C620.1(P) C628.1(P) C631.1(P) C632.1(P) C634.1(P) C674.1(P) C675.1(P) C677.1(P) C690.1(P) L9.1 R101.2(N2) U26.G8(VCCPINT) U26.H9(VCCPINT) U26.H11(VCCBRAM) U26.J8(VCCPINT) U26.J10(VCCBRAM) U26.J12(VCCINT) U26.J14(VCCINT) U26.K13(VCCINT) U26.L8(VCCPINT) U26.L14(VCCINT) U26.M13(VCCINT) U26.N8(VCCPINT) U26.N14(VCCINT) U26.P13(VCCINT) U26.R8(VCCPINT) U26.R14(VCCINT)
VCCINT_EN: C689.1(P) R628.2(N2) U25.3(EN) U42.5(EN)
VCCPLL: C57.1(P) C585.1(P) FB2.1(N1) U26.H10(VCCPLL)
VDD_PLL: C685.2(N) C686.1(P) FB500.1(N1) U35.H2(VDD_PLLM) U35.J2(VDD_PLLD)
VSS_PLL: C685.1(P) C686.2(N) FB501.1(N1) U35.G3(VSS_PLLM) U35.H3(VSS_PLLD)
ACT_SYNC: U35.L15(GPIO_17) ; also on sheet 16
CAL_PWR: R518.2(N2) U35.J15(GPIO_13)
CMP_OUT: U35.A12(CMP_OUT) ; also on sheet 8
CMP_PWM: TP13.1(P1) U35.A15(CMP_PWM)
DMD_DEN_ARSTZ: J12.35(P35) TP_ARZ.1(P1) U35.B1(DMD_DEN_ARSTZ)
DMD_HS_CLK_N: J12.20(P20) TP_CKN.1(P1) U35.B7(DMD_HS_CLK_N)
DMD_HS_CLK_P: J12.21(P21) TP_CKP.1(P1) U35.A7(DMD_HS_CLK_P)
DMD_HS_WDATAA_N: J12.10(P10) TP_AN.1(P1) U35.B11(DMD_HS_WDATAA_N)
DMD_HS_WDATAA_P: J12.11(P11) TP_AP.1(P1) U35.A11(DMD_HS_WDATAA_P)
DMD_HS_WDATAB_N: J12.12(P12) U35.B10(DMD_HS_WDATAB_N)
DMD_HS_WDATAB_P: J12.13(P13) U35.A10(DMD_HS_WDATAB_P)
DMD_HS_WDATAC_N: J12.15(P15) U35.B9(DMD_HS_WDATAC_N)
DMD_HS_WDATAC_P: J12.16(P16) U35.A9(DMD_HS_WDATAC_P)
DMD_HS_WDATAD_N: J12.17(P17) U35.B8(DMD_HS_WDATAD_N)
DMD_HS_WDATAD_P: J12.18(P18) U35.A8(DMD_HS_WDATAD_P)
DMD_HS_WDATAE_N: J12.23(P23) U35.B6(DMD_HS_WDATAE_N)
DMD_HS_WDATAE_P: J12.24(P24) U35.A6(DMD_HS_WDATAE_P)
DMD_HS_WDATAF_N: J12.25(P25) U35.B5(DMD_HS_WDATAF_N)
DMD_HS_WDATAF_P: J12.26(P26) U35.A5(DMD_HS_WDATAF_P)
DMD_HS_WDATAG_N: J12.28(P28) U35.B4(DMD_HS_WDATAG_N)
DMD_HS_WDATAG_P: J12.29(P29) U35.A4(DMD_HS_WDATAG_P)
DMD_HS_WDATAH_N: J12.30(P30) U35.B3(DMD_HS_WDATAH_N)
DMD_HS_WDATAH_P: J12.31(P31) U35.A3(DMD_HS_WDATAH_P)
DMD_LS_CLK: J12.33(P33) R85.1(N1) TP_CLK.1(P1)
DMD_LS_RDATA: J12.36(P36) TP_RD.1(P1) U35.B2(DMD_LS_RDATA)
DMD_LS_WDATA: J12.34(P34) R84.1(N1) TP_WD.1(P1)
FPGA_PWREN: R628.1(N1) U31.1(A) U32.4(Y)
FPGA_RDY: U35.K14(GPIO_14) ; also on sheet 16 17
FPGA_RESETZ: U35.M14(GPIO_18) ; also on sheet 13
GPIO_1: R87.2(N2) R608.1(N1) U35.C15(GPIO_1)
GPIO_2: R88.2(N2) R607.1(N1) U35.D14(GPIO_2)
GPIO_3: R89.2(N2) R606.1(N1) U35.D15(GPIO_3)
GPIO_4: TP15.1(P1) U35.E14(GPIO_4)
GPIO_5: TP14.1(P1) U35.E15(GPIO_5)
GPIO_6: TP16.1(P1) U35.F14(GPIO_6)
GPIO_19: TP17.1(P1) U35.M15(GPIO_19)
INTZ: U32.1(A) ; also on sheet 8 15
LABB_SAMPLE: U35.F15(GPIO_7) ; also on sheet 8
LED_SEL_0: R599.2(N2) TP30.1(P1) U35.B15(LED_SEL_0) ; also on sheet 8
LED_SEL_1: R574.2(N2) TP31.1(P1) U35.B14(LED_SEL_1) ; also on sheet 8
LS2_PWR: J4.1 U35.J14(GPIO_12)
LS_CLK: R85.2(N2) U35.A1(DMD_LS_CLK)
LS_PWR: J3.1 U35.G15(GPIO_9)
LS_WDATA: R84.2(N2) U35.A2(DMD_LS_WDATA)
MTR_SENS_POWER: J6.1 U15.4(Y)
P1P0V_FB: R100.2(N2) R101.1(N1) U42.4(VFB)
P1P0V_SW: C71.1(P) L9.2 U42.2(SW)
P1P0V_VBST: C71.2(N) U42.6(VBST)
P1P1V_DLPA: C53.1(P) C642.1(P) C643.1(P) C647.1(P) C648.1(P) C649.1(P) C651.1(P) C654.1(P) C683.1(P) C684.1(P) C687.1(P) C688.1(P) FB500.2(N2) U35.C3(VDDLP12) U35.C5(VDD) U35.D3(VDD) U35.D5(VDD) U35.D7(VDD) U35.D9(VDD) U35.D12(VDD) U35.D13(VDD) U35.E3(VDD) U35.F13(VDD) U35.H13(VDD) U35.J4(VDD) U35.J12(VDD) U35.K3(VDD) U35.L4(VDD) U35.L12(VDD) U35.L13(VDD) U35.M6(VDD) U35.M9(VDD) U35.M10(VDD) ; also on sheet 8
P1P8V: C54.1(P) C551.1(P) C570.1(P) C577.1(P) C581.1(P) C582.1(P) C583.1(P) C584.1(P) C595.1(P) C597.1(P) C598.1(P) C599.1(P) C600.1(P) C601.1(P) C619.1(P) C622.1(P) C624.1(P) C637.1(P) C638.1(P) C639.1(P) C640.1(P) C679.1(P) U24.1(VOUT) U26.A10(VCCO_MIO1_501) U26.AA10(VCCO_13) U26.AA20(VCCO_33) U26.AB3(VCCO_13) U26.AB13(VCCO_33) U26.B3(VCCO_MIO0_500) U26.B13(VCCO_MIO1_501) U26.C6(VCCO_MIO0_500) U26.D9(VCCO_MIO1_501) U26.E12(VCCO_MIO1_501) U26.R12(VCCO_0) U26.T5(VCCO_13) U26.U8(VCCO_13) U26.U18(VCCO_33) U26.V11(VCCO_13) U26.V21(VCCO_33) U26.W4(VCCO_13) U26.W14(VCCO_33) U26.Y7(VCCO_13) U26.Y17(VCCO_33) ; also on sheet 13 16 17
P1P8V_DLPA: C550.1(P) C604.1(P) C641.1(P) C644.1(P) C645.1(P) C646.1(P) C650.1(P) C653.1(P) C682.1(P) C691.1(P) J12.1(P1) J12.2(P2) J12.39(P39) J12.40(P40) R606.2(N2) R607.2(N2) R608.2(N2) U24.4(VIN) U24.6(VIN) U35.C7(VCC) U35.C9(VCC) U35.D4(VCC) U35.E12(VCC) U35.F12(VCC) U35.K13(VCC) U35.M3(VCC_INTF) U35.M7(VCC_INTF) U35.M11(VCC) U35.N3(VCC_INTF) U35.N7(VCC_INTF) ; also on sheet 8 13 15
P1P8V_PRE: C44.1(P) C45.1(P) C46.1(P) C566.1(P) C571.1(P) C591.1(P) C593.1(P) C596.1(P) C602.1(P) FB2.2(N2) L4.2 R70.2(N2) U26.K9(VCCPAUX) U26.L10(VCCAUX) U26.M9(VCCPAUX) U26.N10(VCCAUX) U26.P9(VCCPAUX) U26.P11(VCCAUX) U26.R10(VCCAUX) U26.T9(VCCPAUX) U31.2(B) ; also on sheet 17
P1P8V_PRE_FB: C44.2(N) R69.2(N2) R70.1(N1) U25.4(FB)
P1P8V_PRE_SW: L4.1 U25.5(SW)
P1P35V_FB: C40.2(N) R65.1(N1) R66.1(N1) U21.4(FB)
P1P35V_SW: L3.1 U21.5(SW)
P2P5V: C621.1(P) C623.1(P) C625.1(P) C626.1(P) C627.1(P) C671.1(P) C672.1(P) C673.1(P) U26.A20(VCCO_35) U26.C16(VCCO_35) U26.D19(VCCO_35) U26.E22(VCCO_35) U26.F15(VCCO_35) U26.G18(VCCO_35) U26.H21(VCCO_35) U39.1(VOUT) ; also on sheet 17
P2P5V_DLPA: U39.4(VIN) U39.6(VIN) ; also on sheet 8 13
P3P3V: C48.1(P) C58.1(P) C564.1(P) C629.1(P) C630.1(P) C633.1(P) C635.1(P) C636.1(P) U26.K17(VCCO_34) U26.L20(VCCO_34) U26.N16(VCCO_34) U26.P19(VCCO_34) U26.R22(VCCO_34) U26.T15(VCCO_34) U34.1(VOUT) ; also on sheet 10 11 16
P3P3V_DLPA: U15.5(PWR) U34.4(VIN) U34.6(VIN) ; also on sheet 8
P3P3V_SB: C652.1(P) R540.1(N1) U31.5(VCC) U32.5(VCC) U35.D11(VCC_FLSH) ; also on sheet 9 15 17
PROJ_ON: R539.2(N2) U32.2(B) U35.G14(GPIO_8) ; also on sheet 8 9
PWRON_SEQ: R540.2(N2) U21.3(EN) U24.3(ON) U31.4(Y) U34.3(ON) U39.3(ON)
RC_CHARGE: U35.H14(GPIO_10) ; also on sheet 8
SENS_FOCUS: C515.1(P) J6.2 R517.2(N2) R518.1(N1) ; also on sheet 8
SENS_LABB: C500.1(P) J4.2 ; also on sheet 8
SENS_THERM: C514.1(P) J7.2 R516.2(N2) ; also on sheet 8
SENS_WPC: C501.1(P) J3.2 ; also on sheet 8
SPI1_CLK: R87.1(N1) ; also on sheet 8
SPI1_CSZ0: R89.1(N1) ; also on sheet 8
SPI1_DIN: U35.C14(GPIO_0) ; also on sheet 8
SPI1_DOUT: R88.1(N1) ; also on sheet 8
SUBFRAME_1: U35.K15(GPIO_15) ; also on sheet 13
SUBFRAME_2: U35.L14(GPIO_16) ; also on sheet 13
THERM_PWR: J7.1 R37.2(N2) U35.H15(GPIO_11)
THERM_SENS: R37.1(N1) R516.1(N1) RT1.1
TSTPT_7: U15.2(A) ; also on sheet 15
VBIAS: C606.1(P) J12.6(P6) ; also on sheet 8
VOFS: C43.1(P) J12.5(P5) ; also on sheet 8
VRST: C605.1(P) J12.7(P7) ; also on sheet 8

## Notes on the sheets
sheet 1
- DMD INTERFACE
sheet 2
- BOARD MOUNTING HOLES
- FPGA
  12V Fan Power
- DAC I/F
- PDAT BUS
- - SHUTDOWN WHEN FAST PARK DETECTED.
  - INTZ GOING HIGH ENABLES POWER TO FPGA.
- PARALLEL IN
- FPD-LINK
- LOAD SWITCHES FOR I/O POWER
- Vin: 4.5V~17V
- 1.00V
- 2A Out
- Vin: 2V-6V
- 1.35V
- 300mA Out
- Vin: 2V-6V
- 1.8V
- 600mA Out
- DGND = GND
- FPGA POWER
sheet 3
- Revisions
- Rev. A: Initial Release
- REVISION NOTES
sheet 4
- FOCUS
- (MTR_SENS_PWR)
- LABB
- WPC
- TEMP
- DLPC3436 GPIO, SPI1 BUS & LED_SEL
sheet 5
- DLPC3436 1080p DISPLAY BOARD
  REFERENCE DESIGN
sheet 7
- ASIC POWER
